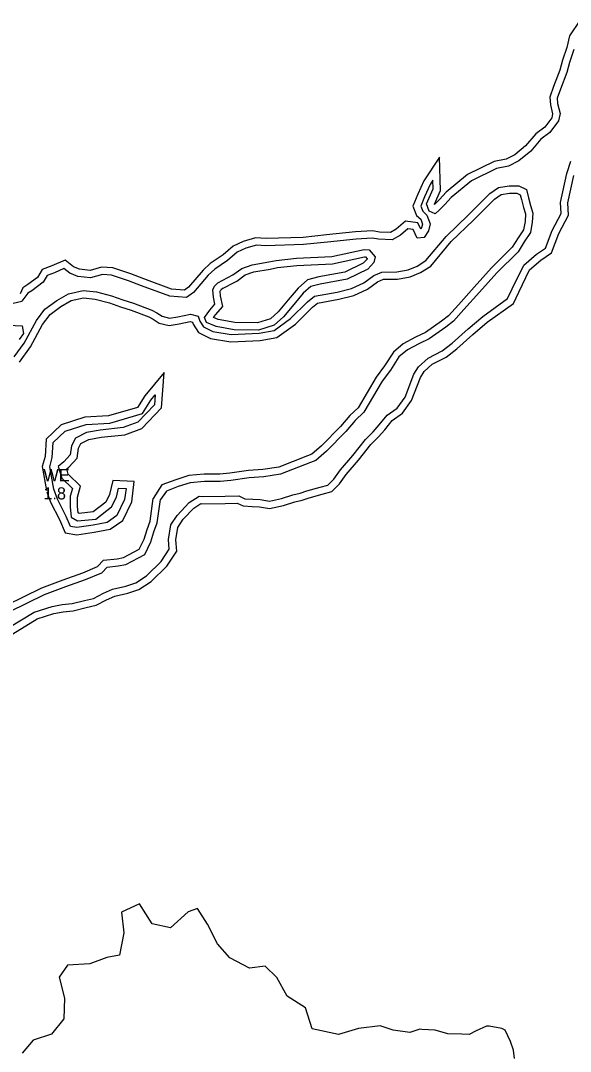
# Model space of a CAD drawing. Extents: x 2160437 to 2172832, y 205694 to 212444.
# Drawn here: x 2165428.5 to 2165654.9, y 210032.9 to 210457.5 of the extents above; entities that cross this region are included whole.
import ezdxf

# ---------------------------------------------------------------- set-up
doc = ezdxf.new("R2010")
doc.units = 0
for name, color, linetype in [('RD_EX_H2O', 7, 'Continuous'), ('RD_EX_H2O_Pond', 7, 'Continuous'), ('RD_EX_H2O_txCode', 7, 'Continuous'), ('RD_EX_VEG_ShrubLine', 7, 'Continuous')]:
    doc.layers.add(name, color=color, linetype=linetype)

msp = doc.modelspace()

# ---------------------------------------------------------------- linework, layer by layer
at = {"layer": 'RD_EX_H2O'}
for points in [[(2165656.32, 210445.49), (2165654.48, 210440.26), (2165653.44, 210436.08), (2165650.83, 210429.26), (2165649.46, 210425.55), (2165649.67, 210423.27), (2165650.69, 210419.14), (2165650.03, 210416.16), (2165646.47, 210411.39), (2165642.78, 210408.59), (2165638.58, 210403.65), (2165633.61, 210399.68), (2165629.47, 210397.5), (2165624.42, 210396.51), (2165614.19, 210391.49), (2165605.78, 210384.55), (2165603.19, 210381.75), (2165600.85, 210379.31), (2165599.17, 210377.83), (2165596.8, 210378.97), (2165595.66, 210382), (2165598.43, 210388.11), (2165598.31, 210391.7), (2165597.14, 210389.94), (2165594.84, 210384.82), (2165593.27, 210381.02), (2165594.08, 210378.92), (2165595.83, 210377.31), (2165597.14, 210373.73), (2165596.44, 210370.86), (2165594.74, 210368.17), (2165591.83, 210367.9), (2165590.11, 210371.39), (2165587.98, 210371.65), (2165584.9, 210369.03), (2165581.52, 210367.08), (2165575.9, 210367.39), (2165573.2, 210367.84), (2165566.65, 210367.47), (2165554.82, 210366.25), (2165545.02, 210365.17), (2165529.5, 210364.71), (2165525.58, 210364.92), (2165521.24, 210363.7), (2165517.67, 210362.02), (2165513.65, 210358.62), (2165508.45, 210355), (2165505.76, 210352.59), (2165499.64, 210345.42), (2165496.77, 210343.39), (2165489.9, 210343.92), (2165478.2, 210348.21), (2165472.89, 210350.3), (2165465.83, 210352.62), (2165462.12, 210352.89), (2165457.3, 210351.49), (2165451.99, 210352.07), (2165448.75, 210353.36), (2165446.31, 210355.28), (2165442.39, 210353.6), (2165439.35, 210352.5), (2165437.73, 210349.65), (2165433.08, 210346.2), (2165431.4, 210345.18), (2165429, 210341.93)], [(2165492.9, 210253.66), (2165497.83, 210258.97), (2165502.05, 210261.59), (2165503.3, 210261.43), (2165512.72, 210261.59), (2165518.28, 210261.64), (2165520.81, 210260.52), (2165524.05, 210260.32), (2165527.18, 210260.22), (2165530.95, 210259.47), (2165535.89, 210260.54), (2165540.53, 210262.08), (2165543.57, 210262.78), (2165546.35, 210263.79), (2165551.84, 210265.28), (2165555.06, 210266.13), (2165557.46, 210268.57), (2165560.17, 210272.37), (2165565.29, 210278.31), (2165570.46, 210284.85), (2165573.64, 210288.03), (2165576.17, 210290.89), (2165579.48, 210294.91), (2165583.6, 210297.85), (2165586.8, 210302.36), (2165590.42, 210311.75), (2165592.3, 210314.9), (2165596.28, 210318.41), (2165602.08, 210321.41), (2165606.24, 210324.57), (2165612.78, 210330.48), (2165618.84, 210335.55), (2165629.06, 210342.94), (2165630.92, 210346.92), (2165635.7, 210356.69), (2165640.91, 210361.21), (2165644.71, 210363.69), (2165647.36, 210370.96), (2165651.14, 210378), (2165650.82, 210382.55), (2165653.47, 210394.47), (2165655.03, 210399.59)], [(2165429.89, 210324.54), (2165434.93, 210333.87), (2165438.43, 210338.52), (2165443.39, 210342.2), (2165448.21, 210344.97), (2165454.23, 210346.26), (2165459.75, 210345.67), (2165465.9, 210344.05), (2165470.54, 210342.41), (2165474.93, 210341.03), (2165482.53, 210338.11), (2165484.62, 210337.01), (2165486.74, 210335.65), (2165489.73, 210334.89), (2165493.25, 210335.46), (2165498.39, 210336.56), (2165501.59, 210335.74), (2165502.23, 210333.69), (2165503.84, 210331.36), (2165507.63, 210329.38), (2165515.25, 210328.1), (2165526.77, 210328.68), (2165532.84, 210329.74), (2165539.68, 210334.76), (2165546.62, 210341.63), (2165549.46, 210343.91), (2165558.84, 210345.65), (2165564.75, 210347.1), (2165569.83, 210349.38), (2165573.93, 210352.47), (2165577.29, 210353.89), (2165583.42, 210353.93), (2165588.05, 210354.78), (2165591.77, 210356.34), (2165595.36, 210358.64), (2165603.68, 210368.46), (2165612.91, 210377.4), (2165621.69, 210386.24), (2165625.29, 210388.69), (2165629.64, 210389.43), (2165633.61, 210389.41), (2165636.87, 210387.84), (2165637.68, 210384.46), (2165638.5, 210381.25), (2165639.39, 210378.19), (2165639.21, 210374.4), (2165638.49, 210370.14), (2165635.91, 210366.28), (2165633.34, 210362.17), (2165624.56, 210353.6), (2165617.46, 210345.63), (2165611.02, 210338.39), (2165606.82, 210333.66), (2165603.65, 210331.23), (2165596.68, 210326.32), (2165592.45, 210324.36), (2165587.76, 210321.77), (2165584.31, 210318.92), (2165580.79, 210313.48), (2165577.41, 210308.89), (2165569.88, 210296.11), (2165566.27, 210292.77), (2165562.47, 210288.25), (2165554.4, 210280.11), (2165550, 210276.28), (2165547.8, 210275.37), (2165535.52, 210270.66), (2165528.6, 210269.56), (2165522.61, 210269.16), (2165515.06, 210268.08), (2165510.72, 210267.63), (2165504.2, 210267.59), (2165498.35, 210267.1), (2165493.36, 210265.5), (2165488.56, 210263.68), (2165486.09, 210260.25)], [(2165425.44, 210341.05), (2165429, 210341.93)], [(2165423.35, 210332.02), (2165429.16, 210331.75), (2165429.66, 210328.63), (2165427.91, 210326.08)], [(2165425.8, 210318.91), (2165429.89, 210324.54)], [(2165424.06, 210214.03), (2165438.35, 210221), (2165447.08, 210224.32), (2165455.23, 210227.17), (2165461.89, 210230.03), (2165464.04, 210232.31), (2165468.58, 210232.82), (2165471.77, 210233.38), (2165479.57, 210237.59), (2165482.13, 210242.69), (2165483.39, 210246.87), (2165484.76, 210250.52), (2165486.09, 210260.25)], [(2165423.57, 210207.41), (2165434, 210213.82), (2165441.42, 210216.1), (2165445.56, 210216.93), (2165449.63, 210217.31), (2165454.77, 210218.63), (2165458.48, 210219.44), (2165462.59, 210221.6), (2165466.27, 210223.21), (2165471.75, 210224.55), (2165475.86, 210225.85), (2165480.36, 210228.7), (2165486.34, 210234.68), (2165489.71, 210239.66), (2165489.39, 210243.67), (2165490.37, 210249.79), (2165492.9, 210253.66)]]:
    msp.add_lwpolyline(points, dxfattribs=at)
msp.add_lwpolyline([(2165509.69, 210349.41), (2165515.86, 210352.73), (2165519.51, 210355.36), (2165523.82, 210356.83), (2165530.67, 210358.08), (2165533.77, 210358.66), (2165542.05, 210359.63), (2165556.58, 210360.29), (2165569.9, 210363.16), (2165572.04, 210362.99), (2165574.5, 210360.1), (2165573.99, 210357.81), (2165571.42, 210355.05), (2165562.96, 210350.96), (2165551.9, 210348.94), (2165548, 210347.97), (2165544.89, 210345.22), (2165541.04, 210340.51), (2165536.71, 210335.42), (2165532.86, 210332), (2165526.5, 210329.97), (2165516.45, 210330.08), (2165508.96, 210331.43), (2165504.99, 210333.16), (2165504.13, 210335.13), (2165506.38, 210338.17), (2165508.52, 210340.58), (2165507.86, 210343.6), (2165507.67, 210346.56), (2165508.31, 210348.01)], close=True, dxfattribs=at)
at = {"layer": 'RD_EX_H2O_Pond'}
msp.add_lwpolyline([(2165442.13, 210264.4), (2165440.45, 210273.59), (2165441.5, 210277.44), (2165441.92, 210283.67), (2165446.79, 210288.28), (2165455.48, 210291.14), (2165465.22, 210291.61), (2165478.6, 210295.57), (2165482.1, 210301.15), (2165483.89, 210303.29), (2165483.56, 210299.18), (2165476.73, 210292.02), (2165470.7, 210289.78), (2165461.21, 210288.78), (2165455.56, 210287.81), (2165451.11, 210285.47), (2165449.37, 210282.34), (2165448.88, 210278.55), (2165446.31, 210275.73), (2165443.97, 210273.83), (2165445.47, 210268.97), (2165449.79, 210264.78), (2165448.88, 210261.52), (2165448.84, 210257.11), (2165449.33, 210252.94), (2165451.88, 210251.39), (2165459.47, 210252.15), (2165465.94, 210257.14), (2165467.98, 210261.21), (2165468.79, 210264.92), (2165471.89, 210264.75), (2165471.29, 210260.16), (2165468.14, 210253.59), (2165464.12, 210250.75), (2165458.31, 210249.67), (2165451.61, 210248.63), (2165448.94, 210249.09), (2165447.21, 210253.16), (2165443.59, 210260.27)], close=True, dxfattribs=at)
at = {"layer": 'RD_EX_VEG_ShrubLine'}
for points in [[(2165658.86, 210457.45), (2165654.48, 210451.17), (2165653.43, 210446.31), (2165651.61, 210441.12), (2165650.57, 210436.98), (2165648.02, 210430.32), (2165646.41, 210425.95), (2165646.71, 210422.77), (2165647.61, 210419.1), (2165647.24, 210417.44), (2165644.32, 210413.52), (2165640.7, 210410.79), (2165636.48, 210405.82), (2165631.96, 210402.21), (2165628.46, 210400.36), (2165623.45, 210399.38), (2165612.55, 210394.03), (2165603.71, 210386.74), (2165601, 210383.8), (2165598.98, 210381.7), (2165598.9, 210381.9), (2165601.45, 210387.51), (2165601, 210401.17), (2165594.51, 210391.39), (2165592.08, 210386), (2165590.04, 210381.05), (2165591.53, 210377.19), (2165593.26, 210375.6), (2165594.01, 210373.55), (2165593.65, 210372.05), (2165593.36, 210371.6), (2165592.09, 210374.18), (2165587.04, 210374.78), (2165583.17, 210371.49), (2165580.8, 210370.13), (2165576.23, 210370.37), (2165573.36, 210370.85), (2165566.42, 210370.47), (2165554.5, 210369.23), (2165544.81, 210368.17), (2165529.54, 210367.71), (2165525.25, 210367.95), (2165520.18, 210366.52), (2165516.04, 210364.56), (2165511.82, 210361), (2165506.58, 210357.35), (2165503.61, 210354.69), (2165497.61, 210347.65), (2165495.92, 210346.47), (2165490.55, 210346.88), (2165479.27, 210351.02), (2165473.91, 210353.12), (2165466.42, 210355.58), (2165461.8, 210355.92), (2165457.04, 210354.53), (2165452.72, 210355.01), (2165450.27, 210355.99), (2165446.77, 210358.74), (2165441.29, 210356.4), (2165437.29, 210354.94), (2165435.44, 210351.68), (2165431.41, 210348.69), (2165429.34, 210347.43), (2165428.29, 210344.84)], [(2165495.41, 210252.02), (2165499.76, 210256.63), (2165502.73, 210258.48), (2165503.13, 210258.43), (2165512.76, 210258.59), (2165517.66, 210258.64), (2165520.09, 210257.56), (2165523.9, 210257.32), (2165526.84, 210257.22), (2165530.98, 210256.41), (2165536.69, 210257.65), (2165541.34, 210259.19), (2165544.42, 210259.89), (2165547.26, 210260.93), (2165552.61, 210262.38), (2165556.62, 210263.44), (2165559.77, 210266.64), (2165562.53, 210270.52), (2165567.6, 210276.4), (2165572.71, 210282.86), (2165575.83, 210285.98), (2165578.45, 210288.95), (2165581.54, 210292.7), (2165585.75, 210295.7), (2165589.46, 210300.93), (2165593.13, 210310.43), (2165594.64, 210312.96), (2165597.99, 210315.92), (2165603.69, 210318.87), (2165608.15, 210322.26), (2165614.75, 210328.22), (2165620.68, 210333.19), (2165631.45, 210340.97), (2165633.62, 210345.62), (2165638.13, 210354.82), (2165642.72, 210358.81), (2165647.18, 210361.73), (2165650.11, 210369.73), (2165654.2, 210377.35), (2165653.85, 210382.33), (2165656.38, 210393.71)], [(2165427.95, 210316.78), (2165432.53, 210323.12), (2165437.46, 210332.25), (2165440.57, 210336.37), (2165445.03, 210339.68), (2165449.3, 210342.14), (2165454.39, 210343.22), (2165459.21, 210342.71), (2165465.02, 210341.18), (2165469.59, 210339.57), (2165473.94, 210338.2), (2165481.29, 210335.38), (2165483.11, 210334.41), (2165485.53, 210332.86), (2165489.6, 210331.83), (2165493.81, 210332.51), (2165498.33, 210333.48), (2165499.23, 210333.25), (2165499.51, 210332.36), (2165501.79, 210329.04), (2165506.67, 210326.5), (2165515.07, 210325.09), (2165527.1, 210325.7), (2165534.05, 210326.9), (2165541.64, 210332.47), (2165548.62, 210339.39), (2165550.75, 210341.1), (2165559.47, 210342.72), (2165565.73, 210344.25), (2165571.37, 210346.77), (2165575.44, 210349.85), (2165577.91, 210350.89), (2165583.7, 210350.93), (2165588.91, 210351.89), (2165593.17, 210353.67), (2165597.36, 210356.35), (2165605.87, 210366.41), (2165615.02, 210375.27), (2165623.61, 210383.93), (2165626.44, 210385.84), (2165629.88, 210386.43), (2165632.92, 210386.41), (2165634.28, 210385.75), (2165634.76, 210383.74), (2165635.61, 210380.46), (2165636.37, 210377.83), (2165636.22, 210374.72), (2165635.64, 210371.27), (2165633.39, 210367.91), (2165630.98, 210364.07), (2165622.39, 210355.67), (2165615.22, 210347.63), (2165608.77, 210340.39), (2165604.77, 210335.87), (2165601.87, 210333.65), (2165595.17, 210328.93), (2165591.09, 210327.04), (2165586.07, 210324.26), (2165582.05, 210320.94), (2165578.32, 210315.18), (2165574.9, 210310.55), (2165567.52, 210298.01), (2165564.1, 210294.84), (2165560.26, 210290.27), (2165552.35, 210282.3), (2165548.4, 210278.86), (2165546.69, 210278.16), (2165534.75, 210273.57), (2165528.26, 210272.55), (2165522.29, 210272.15), (2165514.69, 210271.06), (2165510.56, 210270.63), (2165504.06, 210270.59), (2165497.76, 210270.06), (2165492.37, 210268.34), (2165486.66, 210266.16), (2165483.11, 210260.66)], [(2165511.1, 210346.77), (2165517.45, 210350.18), (2165520.91, 210352.67), (2165524.58, 210353.92), (2165531.21, 210355.13), (2165534.22, 210355.69), (2165542.29, 210356.64), (2165556.96, 210357.3), (2165570.1, 210360.14), (2165570.56, 210360.1), (2165571.25, 210359.29), (2165571.24, 210359.25), (2165569.61, 210357.51), (2165562.02, 210353.83), (2165551.27, 210351.87), (2165546.56, 210350.71), (2165542.72, 210347.3), (2165538.73, 210342.44), (2165534.56, 210337.52), (2165531.34, 210334.67), (2165526.05, 210332.97), (2165516.74, 210333.08), (2165509.84, 210334.32), (2165507.89, 210335.17), (2165508.71, 210336.28), (2165511.78, 210339.73), (2165510.84, 210344.02), (2165510.71, 210346.01), (2165510.84, 210346.3), (2165511.83, 210347.31)], [(2165439.3, 210263.4), (2165440.83, 210259.09), (2165444.49, 210251.89), (2165446.82, 210246.42), (2165451.59, 210245.59), (2165458.81, 210246.72), (2165465.31, 210247.92), (2165470.5, 210251.58), (2165474.2, 210259.29), (2165475.28, 210267.56), (2165466.4, 210268.06), (2165465.13, 210262.21), (2165463.56, 210259.1), (2165458.32, 210255.05), (2165452.58, 210254.47), (2165452.14, 210254.74), (2165451.84, 210257.27), (2165451.88, 210261.1), (2165453.15, 210265.69), (2165448.11, 210270.59), (2165447.44, 210272.78), (2165448.38, 210273.54), (2165451.73, 210277.23), (2165452.27, 210281.39), (2165453.29, 210283.23), (2165456.54, 210284.93), (2165461.62, 210285.81), (2165471.39, 210286.84), (2165478.42, 210289.45), (2165486.47, 210297.89), (2165487.62, 210312.44), (2165479.66, 210302.92), (2165476.66, 210298.12), (2165464.72, 210294.59), (2165454.93, 210294.12), (2165445.21, 210290.92), (2165439.01, 210285.04), (2165438.53, 210277.95), (2165437.38, 210273.73), (2165439.18, 210263.86)], [(2165422.64, 210216.68), (2165437.16, 210223.75), (2165446.05, 210227.14), (2165454.15, 210229.97), (2165460.14, 210232.54), (2165462.62, 210235.18), (2165468.16, 210235.79), (2165470.77, 210236.25), (2165477.31, 210239.79), (2165479.33, 210243.81), (2165480.54, 210247.83), (2165481.84, 210251.26), (2165483.11, 210260.66)], [(2165425.22, 210204.9), (2165435.24, 210211.06), (2165442.16, 210213.19), (2165446, 210213.95), (2165450.15, 210214.35), (2165455.46, 210215.71), (2165459.52, 210216.59), (2165463.89, 210218.9), (2165467.23, 210220.35), (2165472.56, 210221.66), (2165477.13, 210223.1), (2165482.25, 210226.35), (2165488.66, 210232.76), (2165492.79, 210238.84), (2165492.41, 210243.55), (2165493.23, 210248.69), (2165495.41, 210252.02)], [(2165631.87, 210029.94), (2165631.42, 210033.41), (2165630.25, 210036.92), (2165628.07, 210041.62), (2165626.63, 210042.26), (2165621.45, 210043.29), (2165620.34, 210043.24), (2165616.04, 210041.33), (2165613.17, 210039.79), (2165610.16, 210039.95), (2165604.39, 210040.06), (2165604.39, 210040.06), (2165599.27, 210041.61), (2165599.27, 210041.61), (2165593.75, 210041.88), (2165592.89, 210041.99), (2165588.75, 210040.65), (2165581.88, 210041.53), (2165576.52, 210043.37), (2165567.59, 210042.29), (2165559.44, 210039.85), (2165548.49, 210042.19), (2165545.86, 210050.73), (2165538.23, 210055.55), (2165534.02, 210063.35), (2165529.19, 210068.01), (2165522.79, 210067.07), (2165514.69, 210071.38), (2165509.52, 210077.15), (2165505.49, 210085.23), (2165501.37, 210091.73), (2165497.48, 210090.28), (2165490.21, 210083.74), (2165482.63, 210085.42), (2165477.41, 210093.67), (2165469.98, 210090.13), (2165470.91, 210081.69), (2165469.12, 210072.53), (2165463.92, 210071.49), (2165457, 210068.86), (2165447.73, 210068.36), (2165444.38, 210063.49), (2165446.55, 210054.74), (2165446.23, 210046.31), (2165441.11, 210039.9), (2165433.56, 210037.49), (2165429.05, 210032.18)]]:
    msp.add_lwpolyline(points, dxfattribs=at)

# ---------------------------------------------------------------- texts
at = {"layer": 'RD_EX_H2O_txCode'}
for s, p in [('WE', (2165437.84, 210267.7)), ('1.8', (2165437.84, 210260.2))]:
    msp.add_text(s, height=5, dxfattribs=at).set_placement(p)

doc.saveas('drawing.dxf')
